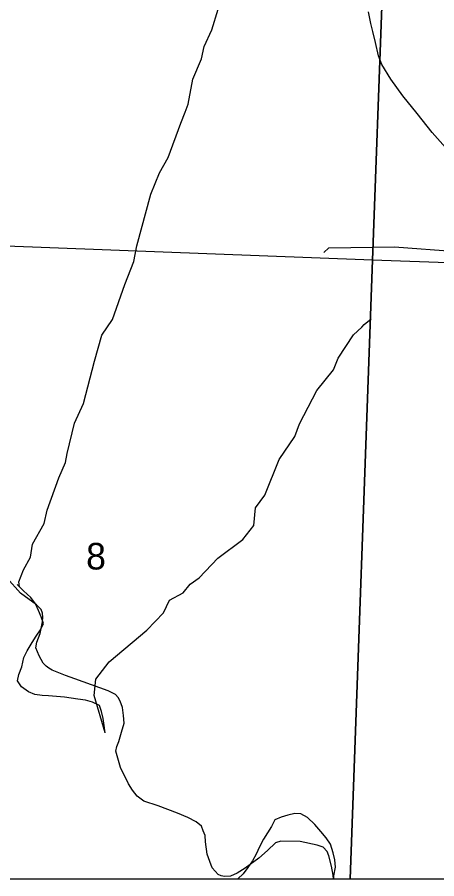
# Model space of a CAD drawing. Extents: x 2.1 to 8.9, y 14.1 to 20.9.
# Drawn here: x 4.863 to 5.524, y 14.1 to 15.459 of the extents above; entities that cross this region are included whole.
import ezdxf

# ---------------------------------------------------------------- set-up
doc = ezdxf.new("R2010")
doc.units = 0
for name, color, linetype in [('Default', 7, 'Continuous'), ('GM_X_City_Street', 7, 'Continuous'), ('GM_X_County_Road_Text', 7, 'Continuous'), ('GM_X_Interchange_Ramps', 7, 'Continuous'), ('GM_X_Rail_Line_Text', 7, 'Continuous'), ('SH_Cut_Line', 7, 'Continuous'), ('SH_Data', 7, 'Continuous'), ('TX_P_Misc', 7, 'Continuous')]:
    doc.layers.add(name, color=color, linetype=linetype)

msp = doc.modelspace()

# ---------------------------------------------------------------- linework, layer by layer
at = {"layer": 'Default'}
for p, q in [((5.4229, 15.0756), (4.4256, 15.1132)), ((5.4229, 15.0756), (5.3878, 14.1)), ((5.3878, 14.1), (5.4229, 15.0756)), ((6.3944, 15.0386), (5.4229, 15.0756)), ((2.1, 14.1), (6.7017, 14.1)), ((4.3897, 14.1), (5.3878, 14.1)), ((5.3878, 14.1), (6.3909, 14.1))]:
    msp.add_line(p, q, dxfattribs=at)
at = {"layer": 'GM_X_City_Street'}
for p, q in [((5.3463, 15.0874), (5.3542, 15.0951)), ((5.3542, 15.0951), (5.4575, 15.0963)), ((5.4575, 15.0963), (5.58, 15.0873)), ((4.8675, 14.5505), (4.846, 14.5744)), ((4.8929, 14.5318), (4.8675, 14.5505)), ((4.9002, 14.5245), (4.8929, 14.5318)), ((4.9026, 14.5186), (4.9002, 14.5245)), ((4.9025, 14.5053), (4.9028, 14.5124)), ((4.9028, 14.5124), (4.9026, 14.5186)), ((4.8986, 14.4867), (4.9025, 14.5053)), ((4.8934, 14.4729), (4.8986, 14.4867)), ((4.8917, 14.4644), (4.8934, 14.4729)), ((4.8972, 14.4517), (4.8917, 14.4644)), ((4.9036, 14.44), (4.8972, 14.4517)), ((4.9081, 14.4352), (4.9036, 14.44)), ((4.9124, 14.432), (4.9081, 14.4352)), ((4.9175, 14.429), (4.9124, 14.432)), ((4.9385, 14.4207), (4.9175, 14.429)), ((4.9532, 14.4152), (4.9385, 14.4207)), ((5.0059, 14.3962), (4.9532, 14.4152)), ((5.0175, 14.3908), (5.0059, 14.3962)), ((5.0216, 14.3859), (5.0175, 14.3908)), ((5.0247, 14.3801), (5.0216, 14.3859)), ((5.0284, 14.3701), (5.0247, 14.3801)), ((5.0304, 14.3574), (5.0284, 14.3701)), ((5.0313, 14.3452), (5.0304, 14.3574)), ((5.0269, 14.3312), (5.0313, 14.3452)), ((5.0226, 14.3166), (5.0269, 14.3312)), ((5.018, 14.301), (5.0195, 14.3083)), ((5.0195, 14.3083), (5.0226, 14.3166)), ((5.0257, 14.2754), (5.018, 14.301)), ((5.038, 14.2499), (5.0257, 14.2754)), ((5.0443, 14.2395), (5.038, 14.2499)), ((5.0517, 14.23), (5.0443, 14.2395)), ((5.0624, 14.2226), (5.0517, 14.23)), ((5.0847, 14.215), (5.0624, 14.2226)), ((5.1152, 14.2035), (5.0847, 14.215)), ((5.1319, 14.1968), (5.1152, 14.2035)), ((5.1449, 14.1899), (5.1319, 14.1968)), ((5.153, 14.1829), (5.1449, 14.1899)), ((5.1561, 14.1758), (5.153, 14.1829)), ((5.1591, 14.1683), (5.1561, 14.1758)), ((5.1596, 14.1581), (5.1591, 14.1683)), ((5.1624, 14.1389), (5.1596, 14.1581)), ((5.2786, 14.1595), (5.27, 14.1564)), ((5.309, 14.1585), (5.2786, 14.1595)), ((5.3357, 14.1532), (5.309, 14.1585)), ((5.2573, 14.1446), (5.2435, 14.1325)), ((5.27, 14.1564), (5.2573, 14.1446)), ((5.3452, 14.1496), (5.3357, 14.1532)), ((5.3513, 14.1432), (5.3452, 14.1496)), ((5.1663, 14.1274), (5.1624, 14.1389)), ((5.2435, 14.1325), (5.2222, 14.1165)), ((5.3543, 14.1361), (5.3513, 14.1432)), ((5.3584, 14.1197), (5.3543, 14.1361)), ((5.1702, 14.1171), (5.1663, 14.1274)), ((5.1794, 14.1068), (5.1702, 14.1171)), ((5.3611, 14.1058), (5.3584, 14.1197)), ((5.1845, 14.1045), (5.1794, 14.1068)), ((5.1896, 14.1036), (5.1845, 14.1045)), ((5.1988, 14.1043), (5.1896, 14.1036)), ((5.2097, 14.109), (5.1988, 14.1043)), ((5.2222, 14.1165), (5.2097, 14.109)), ((5.3616, 14.1), (5.3611, 14.1058))]:
    msp.add_line(p, q, dxfattribs=at)
at = {"layer": 'GM_X_Interchange_Ramps'}
for p, q in [((5.4597, 16.0717), (5.4229, 15.0756)), ((5.4229, 15.0756), (5.4597, 16.0717)), ((5.4229, 15.0756), (4.4256, 15.1132)), ((6.3944, 15.0386), (5.4229, 15.0756))]:
    msp.add_line(p, q, dxfattribs=at)
at = {"layer": 'GM_X_Rail_Line_Text'}
for p, q in [((5.4204, 15.4489), (5.4164, 15.4673)), ((5.4233, 15.4361), (5.4204, 15.4489)), ((5.4279, 15.4186), (5.4233, 15.4361)), ((5.4322, 15.3976), (5.4279, 15.4186)), ((5.4376, 15.384), (5.4322, 15.3976)), ((5.4521, 15.3611), (5.4376, 15.384)), ((5.4707, 15.3346), (5.4521, 15.3611)), ((5.4936, 15.3069), (5.4707, 15.3346)), ((5.5171, 15.2768), (5.4936, 15.3069)), ((5.5383, 15.2533), (5.5171, 15.2768))]:
    msp.add_line(p, q, dxfattribs=at)
at = {"layer": 'SH_Cut_Line'}
msp.add_line((2.1, 14.1), (6.7017, 14.1), dxfattribs=at)
at = {"layer": 'SH_Data'}
msp.add_line((2.1, 14.1), (8.9, 14.1), dxfattribs=at)
msp.add_line((2.1, 14.1), (8.9, 14.1), dxfattribs=at)
at = {"layer": 'TX_P_Misc'}
for p, q in [((5.1696, 15.4387), (5.1796, 15.4712)), ((5.1576, 15.4123), (5.1696, 15.4387)), ((5.1534, 15.3928), (5.1576, 15.4123)), ((5.1396, 15.361), (5.1534, 15.3928)), ((5.1324, 15.3218), (5.1396, 15.361)), ((5.1273, 15.3091), (5.1324, 15.3218)), ((5.1204, 15.2915), (5.1273, 15.3091)), ((5.1006, 15.2372), (5.1204, 15.2915)), ((5.087, 15.2134), (5.1006, 15.2372)), ((5.0733, 15.1794), (5.087, 15.2134)), ((5.0513, 15.098), (5.0733, 15.1794)), ((5.0464, 15.0736), (5.0513, 15.098)), ((5.0323, 15.0369), (5.0464, 15.0736)), ((5.0129, 14.9819), (5.0323, 15.0369)), ((4.996, 14.9573), (5.0129, 14.9819)), ((5.4062, 14.9697), (5.4096, 14.9739)), ((5.4096, 14.9739), (5.4211, 14.9832)), ((5.3929, 14.9577), (5.4062, 14.9697)), ((4.9846, 14.916), (4.996, 14.9573)), ((5.3686, 14.9212), (5.3929, 14.9577)), ((5.3617, 14.9024), (5.3686, 14.9212)), ((4.9673, 14.8496), (4.9846, 14.916)), ((5.3351, 14.8701), (5.3617, 14.9024)), ((5.308, 14.8176), (5.3351, 14.8701)), ((4.9527, 14.8186), (4.9673, 14.8496)), ((4.9414, 14.7705), (4.9527, 14.8186)), ((5.3004, 14.7973), (5.308, 14.8176)), ((5.2758, 14.7612), (5.3004, 14.7973)), ((4.9387, 14.7564), (4.9414, 14.7705)), ((4.9281, 14.7323), (4.9387, 14.7564)), ((5.253, 14.7049), (5.2758, 14.7612)), ((4.9098, 14.6814), (4.9281, 14.7323)), ((5.2386, 14.6849), (5.253, 14.7049)), ((4.9049, 14.66), (4.9098, 14.6814)), ((5.2357, 14.6571), (5.2386, 14.6849)), ((4.8869, 14.6274), (4.9049, 14.66)), ((5.2183, 14.6348), (5.2357, 14.6571)), ((5.1791, 14.6053), (5.2183, 14.6348)), ((4.8835, 14.6069), (4.8869, 14.6274)), ((4.8725, 14.5869), (4.8835, 14.6069)), ((5.1498, 14.5744), (5.1791, 14.6053)), ((4.8653, 14.5682), (4.8725, 14.5869)), ((4.866, 14.5603), (4.8653, 14.5682)), ((5.1356, 14.5646), (5.1498, 14.5744)), ((4.8725, 14.554), (4.8623, 14.564)), ((4.8842, 14.5433), (4.8725, 14.554)), ((5.1245, 14.5511), (5.1356, 14.5646)), ((4.8914, 14.5333), (4.8842, 14.5433)), ((5.0933, 14.5195), (5.1028, 14.5394)), ((5.1028, 14.5394), (5.1245, 14.5511)), ((4.8959, 14.5228), (4.8914, 14.5333)), ((4.9004, 14.513), (4.8959, 14.5228)), ((4.9042, 14.5025), (4.9004, 14.513)), ((5.067, 14.492), (5.0933, 14.5195)), ((4.8991, 14.4925), (4.9042, 14.5025)), ((4.8926, 14.4828), (4.8991, 14.4925)), ((5.0074, 14.442), (5.067, 14.492)), ((4.8785, 14.4595), (4.8861, 14.4727)), ((4.8861, 14.4727), (4.8926, 14.4828)), ((4.8728, 14.4487), (4.8785, 14.4595)), ((4.8698, 14.4341), (4.8728, 14.4487)), ((4.8652, 14.4222), (4.8698, 14.4341)), ((4.9867, 14.4147), (5.0074, 14.442)), ((4.8629, 14.4123), (4.8652, 14.4222)), ((4.8693, 14.4026), (4.8629, 14.4123)), ((4.8805, 14.3946), (4.8693, 14.4026)), ((4.9841, 14.3892), (4.9867, 14.4147)), ((4.8902, 14.3907), (4.8805, 14.3946)), ((4.902, 14.3891), (4.8902, 14.3907)), ((4.9119, 14.3883), (4.902, 14.3891)), ((5.0012, 14.3299), (4.9841, 14.3892)), ((4.9371, 14.3861), (4.9119, 14.3883)), ((4.9478, 14.3849), (4.9371, 14.3861)), ((4.9581, 14.3833), (4.9478, 14.3849)), ((4.9703, 14.3814), (4.9581, 14.3833)), ((4.9814, 14.3783), (4.9703, 14.3814)), ((4.9926, 14.3733), (4.9814, 14.3783)), ((4.9956, 14.3635), (4.9926, 14.3733)), ((4.9982, 14.3526), (4.9956, 14.3635)), ((4.9997, 14.3416), (4.9982, 14.3526)), ((5.0012, 14.3299), (4.9997, 14.3416)), ((5.2892, 14.2005), (5.2787, 14.1971)), ((5.3002, 14.2027), (5.2892, 14.2005)), ((5.3101, 14.2023), (5.3002, 14.2027)), ((5.3205, 14.1965), (5.3101, 14.2023)), ((5.269, 14.193), (5.2636, 14.1826)), ((5.2787, 14.1971), (5.269, 14.193)), ((5.3319, 14.1855), (5.3205, 14.1965)), ((5.3414, 14.1744), (5.3319, 14.1855)), ((5.2571, 14.1725), (5.2513, 14.1624)), ((5.2636, 14.1826), (5.2571, 14.1725)), ((5.3497, 14.1647), (5.3414, 14.1744)), ((5.2513, 14.1624), (5.2448, 14.1501)), ((5.3565, 14.1543), (5.3497, 14.1647)), ((5.2448, 14.1501), (5.2395, 14.1389)), ((5.3611, 14.1408), (5.3565, 14.1543)), ((5.2395, 14.1389), (5.2337, 14.128)), ((5.3637, 14.1298), (5.3611, 14.1408)), ((5.2265, 14.1179), (5.2188, 14.1078)), ((5.2337, 14.128), (5.2265, 14.1179)), ((5.3622, 14.1047), (5.3648, 14.1181)), ((5.3648, 14.1181), (5.3637, 14.1298)), ((5.2188, 14.1078), (5.2103, 14.1)), ((5.3619, 14.1), (5.3622, 14.1047))]:
    msp.add_line(p, q, dxfattribs=at)

# ---------------------------------------------------------------- texts
at = {"layer": 'GM_X_County_Road_Text'}
msp.add_text('8', height=0.0419, rotation=0, dxfattribs=at).set_placement((4.9713, 14.5877))

doc.saveas('drawing.dxf')
